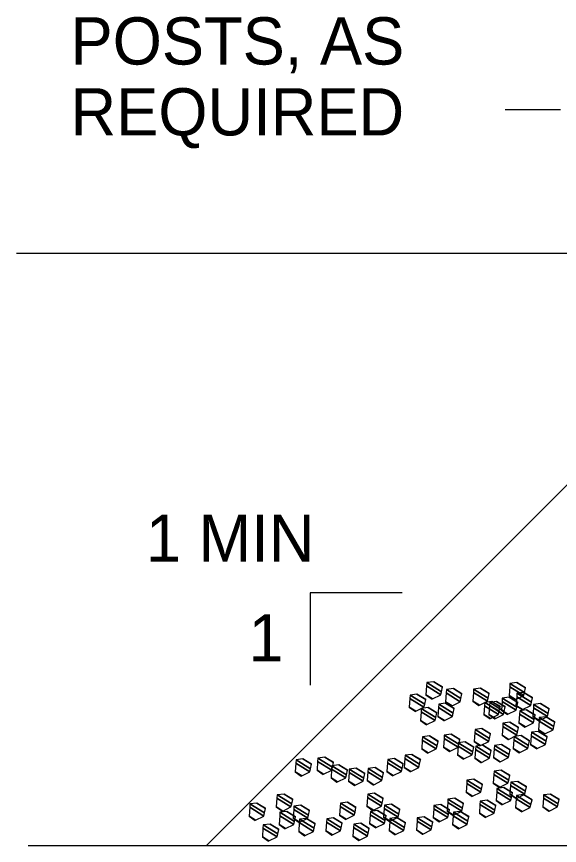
# Model space of a CAD drawing. Extents: x 636462 to 639049, y 299944 to 300538.
# Drawn here: x 637684.5 to 637718.9, y 300291.8 to 300344.3 of the extents above; entities that cross this region are included whole.
import ezdxf

# ---------------------------------------------------------------- set-up
doc = ezdxf.new("R2010")
doc.units = 0
doc.layers.add('Default', color=7, linetype='Continuous')

msp = doc.modelspace()

# ---------------------------------------------------------------- linework, layer by layer
at = {"layer": 'Default'}
for p, q in [((637715.459, 300338.433), (637718.957, 300338.433)), ((637684.462, 300329.325), (637739.67, 300329.325)), ((637696.5, 300291.751), (637727.952, 300323.205)), ((637685.207, 300291.751), (637853.724, 300291.751))]:
    msp.add_line(p, q, dxfattribs=at)
msp.add_lwpolyline([(637708.916, 300307.763), (637703.079, 300307.763), (637703.079, 300301.925)], dxfattribs=at)
for points in [[(637710.468, 300301.866), (637711.365, 300301.31), (637711.408, 300301.503), (637710.484, 300302.076)], [(637710.484, 300302.076), (637711.408, 300301.503), (637711.472, 300301.792), (637710.923, 300302.133)], [(637710.923, 300302.133), (637711.472, 300301.792), (637711.475, 300301.805), (637711.475, 300301.805)], [(637715.737, 300301.808), (637716.626, 300301.257), (637716.67, 300301.452), (637715.752, 300302.022)], [(637715.752, 300302.022), (637716.67, 300301.452), (637716.735, 300301.737), (637716.187, 300302.076)], [(637716.187, 300302.076), (637716.735, 300301.737), (637716.737, 300301.749), (637716.737, 300301.749)], [(637710.427, 300301.31), (637710.844, 300301.051), (637711.365, 300301.31), (637710.468, 300301.866)], [(637711.669, 300300.869), (637712.084, 300300.611), (637712.597, 300300.869), (637711.708, 300301.42)], [(637711.708, 300301.42), (637712.597, 300300.869), (637712.642, 300301.066), (637711.723, 300301.635)], [(637711.723, 300301.635), (637712.642, 300301.066), (637712.707, 300301.356), (637712.162, 300301.694)], [(637712.162, 300301.694), (637712.707, 300301.356), (637712.708, 300301.362), (637712.708, 300301.362)], [(637713.396, 300300.905), (637713.815, 300300.646), (637714.328, 300300.905), (637713.434, 300301.46)], [(637713.434, 300301.46), (637714.328, 300300.905), (637714.371, 300301.098), (637713.449, 300301.67)], [(637713.449, 300301.67), (637714.371, 300301.098), (637714.435, 300301.384), (637713.885, 300301.724)], [(637713.885, 300301.724), (637714.435, 300301.384), (637714.438, 300301.397), (637714.438, 300301.397)], [(637715.698, 300301.257), (637716.115, 300300.998), (637716.626, 300301.257), (637715.737, 300301.808)], [(637716.195, 300301.405), (637717.114, 300300.835), (637717.178, 300301.122), (637716.634, 300301.459)], [(637716.634, 300301.459), (637717.178, 300301.122), (637717.18, 300301.132), (637717.18, 300301.132)], [(637709.369, 300300.513), (637709.783, 300300.256), (637710.3, 300300.513), (637709.408, 300301.065)], [(637709.408, 300301.065), (637710.3, 300300.513), (637710.344, 300300.713), (637709.424, 300301.283)], [(637709.424, 300301.283), (637710.344, 300300.713), (637710.408, 300300.996), (637709.857, 300301.338)], [(637709.857, 300301.338), (637710.408, 300300.996), (637710.411, 300301.01), (637710.411, 300301.01)], [(637710.811, 300301.035), (637710.811, 300301.035), (637710.844, 300301.051), (637710.427, 300301.31)], [(637713.78, 300300.628), (637713.78, 300300.628), (637713.815, 300300.646), (637713.396, 300300.905)], [(637715.249, 300300.883), (637716.141, 300300.331), (637716.184, 300300.525), (637715.265, 300301.095)], [(637715.265, 300301.095), (637716.184, 300300.525), (637716.248, 300300.811), (637715.704, 300301.148)], [(637716.08, 300300.98), (637716.08, 300300.98), (637716.115, 300300.998), (637715.698, 300301.257)], [(637715.704, 300301.148), (637716.248, 300300.811), (637716.25, 300300.82), (637716.25, 300300.82)], [(637716.136, 300300.634), (637716.551, 300300.377), (637717.069, 300300.634), (637716.179, 300301.186)], [(637716.179, 300301.186), (637717.069, 300300.634), (637717.114, 300300.835), (637716.195, 300301.405)], [(637709.754, 300300.242), (637709.754, 300300.242), (637709.783, 300300.256), (637709.369, 300300.513)], [(637710.115, 300300.227), (637711.007, 300299.673), (637711.051, 300299.874), (637710.132, 300300.444)], [(637710.132, 300300.444), (637711.051, 300299.874), (637711.113, 300300.162), (637710.571, 300300.499)], [(637710.571, 300300.499), (637711.113, 300300.162), (637711.115, 300300.171), (637711.115, 300300.171)], [(637711.179, 300299.938), (637711.593, 300299.682), (637712.114, 300299.938), (637711.22, 300300.492)], [(637711.22, 300300.492), (637712.114, 300299.938), (637712.156, 300300.136), (637711.236, 300300.707)], [(637711.236, 300300.707), (637712.156, 300300.136), (637712.219, 300300.426), (637711.675, 300300.764)], [(637712.053, 300300.596), (637712.053, 300300.596), (637712.084, 300300.611), (637711.669, 300300.869)], [(637711.675, 300300.764), (637712.219, 300300.426), (637712.221, 300300.436), (637712.221, 300300.436)], [(637714.102, 300300.062), (637714.521, 300299.802), (637715.032, 300300.062), (637714.143, 300300.613)], [(637714.143, 300300.613), (637715.032, 300300.062), (637715.076, 300300.257), (637714.158, 300300.826)], [(637714.158, 300300.826), (637715.076, 300300.257), (637715.141, 300300.546), (637714.597, 300300.883)], [(637714.411, 300300.062), (637714.829, 300299.803), (637715.346, 300300.062), (637714.452, 300300.616)], [(637714.452, 300300.616), (637715.346, 300300.062), (637715.389, 300300.255), (637714.468, 300300.826)], [(637714.468, 300300.826), (637715.389, 300300.255), (637715.454, 300300.541), (637714.903, 300300.883)], [(637714.597, 300300.883), (637715.141, 300300.546), (637715.143, 300300.555), (637715.143, 300300.555)], [(637714.903, 300300.883), (637715.454, 300300.541), (637715.457, 300300.555), (637715.457, 300300.555)], [(637715.208, 300300.331), (637715.625, 300300.072), (637716.141, 300300.331), (637715.249, 300300.883)], [(637716.523, 300300.363), (637716.523, 300300.363), (637716.551, 300300.377), (637716.136, 300300.634)], [(637717.196, 300299.93), (637717.613, 300299.672), (637718.131, 300299.93), (637717.238, 300300.484)], [(637717.238, 300300.484), (637718.131, 300299.93), (637718.175, 300300.128), (637717.255, 300300.699)], [(637717.255, 300300.699), (637718.175, 300300.128), (637718.239, 300300.41), (637717.692, 300300.749)], [(637717.692, 300300.749), (637718.239, 300300.41), (637718.242, 300300.424), (637718.242, 300300.424)], [(637710.073, 300299.673), (637710.488, 300299.416), (637711.007, 300299.673), (637710.115, 300300.227)], [(637711.564, 300299.667), (637711.564, 300299.667), (637711.593, 300299.682), (637711.179, 300299.938)], [(637714.488, 300299.785), (637714.488, 300299.785), (637714.521, 300299.802), (637714.102, 300300.062)], [(637714.794, 300299.785), (637714.794, 300299.785), (637714.829, 300299.803), (637714.411, 300300.062)], [(637715.592, 300300.056), (637715.592, 300300.056), (637715.625, 300300.072), (637715.208, 300300.331)], [(637716.312, 300299.53), (637716.729, 300299.272), (637717.245, 300299.53), (637716.353, 300300.083)], [(637716.353, 300300.083), (637717.245, 300299.53), (637717.289, 300299.728), (637716.369, 300300.298)], [(637716.369, 300300.298), (637717.289, 300299.728), (637717.352, 300300.017), (637716.81, 300300.353)], [(637716.81, 300300.353), (637717.352, 300300.017), (637717.354, 300300.025), (637717.354, 300300.025)], [(637717.583, 300299.657), (637717.583, 300299.657), (637717.613, 300299.672), (637717.196, 300299.93)], [(637717.595, 300299.639), (637718.483, 300299.089), (637718.529, 300299.288), (637717.611, 300299.858)], [(637717.611, 300299.858), (637718.529, 300299.288), (637718.595, 300299.574), (637718.046, 300299.914)], [(637718.046, 300299.914), (637718.595, 300299.574), (637718.598, 300299.587), (637718.598, 300299.587)], [(637710.459, 300299.402), (637710.459, 300299.402), (637710.488, 300299.416), (637710.073, 300299.673)], [(637715.291, 300299.292), (637716.185, 300298.737), (637716.229, 300298.933), (637715.305, 300299.506)], [(637715.305, 300299.506), (637716.229, 300298.933), (637716.293, 300299.221), (637715.746, 300299.56)], [(637715.746, 300299.56), (637716.293, 300299.221), (637716.294, 300299.227), (637716.294, 300299.227)], [(637716.699, 300299.257), (637716.699, 300299.257), (637716.729, 300299.272), (637716.312, 300299.53)], [(637717.556, 300299.089), (637717.969, 300298.833), (637718.483, 300299.089), (637717.595, 300299.639)], [(637711.59, 300298.751), (637712.513, 300298.179), (637712.577, 300298.47), (637712.029, 300298.81)], [(637712.029, 300298.81), (637712.577, 300298.47), (637712.579, 300298.48), (637712.579, 300298.48)], [(637713.481, 300298.337), (637713.895, 300298.08), (637714.415, 300298.337), (637713.523, 300298.89)], [(637713.523, 300298.89), (637714.415, 300298.337), (637714.46, 300298.535), (637713.54, 300299.105)], [(637713.54, 300299.105), (637714.46, 300298.535), (637714.524, 300298.822), (637713.976, 300299.162)], [(637713.976, 300299.162), (637714.524, 300298.822), (637714.527, 300298.834), (637714.527, 300298.834)], [(637715.253, 300298.737), (637715.667, 300298.48), (637716.185, 300298.737), (637715.291, 300299.292)], [(637717.105, 300298.712), (637717.997, 300298.159), (637718.041, 300298.359), (637717.121, 300298.929)], [(637717.121, 300298.929), (637718.041, 300298.359), (637718.105, 300298.648), (637717.562, 300298.984)], [(637717.939, 300298.818), (637717.939, 300298.818), (637717.969, 300298.833), (637717.556, 300299.089)], [(637717.562, 300298.984), (637718.105, 300298.648), (637718.106, 300298.656), (637718.106, 300298.656)], [(637710.154, 300297.873), (637710.572, 300297.614), (637711.082, 300297.873), (637710.193, 300298.425)], [(637710.193, 300298.425), (637711.082, 300297.873), (637711.128, 300298.07), (637710.209, 300298.64)], [(637710.209, 300298.64), (637711.128, 300298.07), (637711.193, 300298.353), (637710.645, 300298.693)], [(637710.645, 300298.693), (637711.193, 300298.353), (637711.196, 300298.363), (637711.196, 300298.363)], [(637711.537, 300297.985), (637711.952, 300297.728), (637712.47, 300297.985), (637711.575, 300298.539)], [(637711.575, 300298.539), (637712.47, 300297.985), (637712.513, 300298.179), (637711.59, 300298.751)], [(637712.46, 300298.048), (637713.352, 300297.495), (637713.395, 300297.694), (637712.476, 300298.264)], [(637712.476, 300298.264), (637713.395, 300297.694), (637713.459, 300297.985), (637712.919, 300298.32)], [(637712.919, 300298.32), (637713.459, 300297.985), (637713.461, 300297.993), (637713.461, 300297.993)], [(637713.865, 300298.066), (637713.865, 300298.066), (637713.895, 300298.08), (637713.481, 300298.337)], [(637715.639, 300298.466), (637715.639, 300298.466), (637715.667, 300298.48), (637715.253, 300298.737)], [(637715.961, 300297.896), (637716.376, 300297.638), (637716.891, 300297.896), (637716.001, 300298.447)], [(637716.001, 300298.447), (637716.891, 300297.896), (637716.936, 300298.095), (637716.017, 300298.664)], [(637716.017, 300298.664), (637716.936, 300298.095), (637717.001, 300298.382), (637716.454, 300298.721)], [(637716.454, 300298.721), (637717.001, 300298.382), (637717.002, 300298.389), (637717.002, 300298.389)], [(637717.065, 300298.159), (637717.479, 300297.902), (637717.997, 300298.159), (637717.105, 300298.712)], [(637710.54, 300297.598), (637710.54, 300297.598), (637710.572, 300297.614), (637710.154, 300297.873)], [(637711.924, 300297.714), (637711.924, 300297.714), (637711.952, 300297.728), (637711.537, 300297.985)], [(637712.421, 300297.495), (637712.837, 300297.238), (637713.352, 300297.495), (637712.46, 300298.048)], [(637713.527, 300297.279), (637713.945, 300297.02), (637714.46, 300297.279), (637713.567, 300297.832)], [(637713.567, 300297.832), (637714.46, 300297.279), (637714.503, 300297.472), (637713.582, 300298.043)], [(637713.582, 300298.043), (637714.503, 300297.472), (637714.568, 300297.764), (637714.023, 300298.102)], [(637714.023, 300298.102), (637714.568, 300297.764), (637714.569, 300297.768), (637714.569, 300297.768)], [(637714.719, 300297.319), (637715.133, 300297.062), (637715.655, 300297.319), (637714.761, 300297.874)], [(637714.761, 300297.874), (637715.655, 300297.319), (637715.698, 300297.519), (637714.777, 300298.09)], [(637714.777, 300298.09), (637715.698, 300297.519), (637715.759, 300297.808), (637715.216, 300298.144)], [(637715.216, 300298.144), (637715.759, 300297.808), (637715.76, 300297.815), (637715.76, 300297.815)], [(637716.345, 300297.623), (637716.345, 300297.623), (637716.376, 300297.638), (637715.961, 300297.896)], [(637717.451, 300297.888), (637717.451, 300297.888), (637717.479, 300297.902), (637717.065, 300298.159)], [(637702.187, 300297.184), (637703.111, 300296.611), (637703.174, 300296.895), (637702.624, 300297.236)], [(637702.624, 300297.236), (637703.174, 300296.895), (637703.176, 300296.905), (637703.176, 300296.905)], [(637703.556, 300297.08), (637704.449, 300296.527), (637704.492, 300296.724), (637703.571, 300297.295)], [(637703.571, 300297.295), (637704.492, 300296.724), (637704.556, 300297.014), (637704.012, 300297.352)], [(637704.012, 300297.352), (637704.556, 300297.014), (637704.558, 300297.024), (637704.558, 300297.024)], [(637707.998, 300297.208), (637708.918, 300296.638), (637708.985, 300296.923), (637708.433, 300297.265)], [(637708.433, 300297.265), (637708.985, 300296.923), (637708.987, 300296.933), (637708.987, 300296.933)], [(637709.05, 300296.702), (637709.461, 300296.448), (637709.978, 300296.702), (637709.087, 300297.255)], [(637709.087, 300297.255), (637709.978, 300296.702), (637710.023, 300296.9), (637709.102, 300297.471)], [(637709.102, 300297.471), (637710.023, 300296.9), (637710.088, 300297.186), (637709.537, 300297.528)], [(637709.537, 300297.528), (637710.088, 300297.186), (637710.091, 300297.198), (637710.091, 300297.198)], [(637712.805, 300297.222), (637712.805, 300297.222), (637712.837, 300297.238), (637712.421, 300297.495)], [(637713.91, 300297.002), (637713.91, 300297.002), (637713.945, 300297.02), (637713.527, 300297.279)], [(637715.105, 300297.048), (637715.105, 300297.048), (637715.133, 300297.062), (637714.719, 300297.319)], [(637702.135, 300296.415), (637702.55, 300296.158), (637703.067, 300296.415), (637702.173, 300296.97)], [(637702.173, 300296.97), (637703.067, 300296.415), (637703.111, 300296.611), (637702.187, 300297.184)], [(637703.516, 300296.527), (637703.931, 300296.269), (637704.449, 300296.527), (637703.556, 300297.08)], [(637704.442, 300296.594), (637705.334, 300296.041), (637705.379, 300296.236), (637704.457, 300296.808)], [(637704.457, 300296.808), (637705.379, 300296.236), (637705.443, 300296.522), (637704.891, 300296.864)], [(637704.891, 300296.864), (637705.443, 300296.522), (637705.446, 300296.533), (637705.446, 300296.533)], [(637706.758, 300296.63), (637707.676, 300296.06), (637707.741, 300296.349), (637707.197, 300296.686)], [(637707.197, 300296.686), (637707.741, 300296.349), (637707.743, 300296.359), (637707.743, 300296.359)], [(637707.937, 300296.44), (637708.354, 300296.181), (637708.872, 300296.44), (637707.981, 300296.992)], [(637707.981, 300296.992), (637708.872, 300296.44), (637708.918, 300296.638), (637707.998, 300297.208)], [(637709.428, 300296.431), (637709.428, 300296.431), (637709.461, 300296.448), (637709.05, 300296.702)], [(637702.519, 300296.142), (637702.519, 300296.142), (637702.55, 300296.158), (637702.135, 300296.415)], [(637703.898, 300296.253), (637703.898, 300296.253), (637703.931, 300296.269), (637703.516, 300296.527)], [(637704.404, 300296.041), (637704.819, 300295.784), (637705.334, 300296.041), (637704.442, 300296.594)], [(637705.508, 300295.823), (637705.926, 300295.564), (637706.439, 300295.823), (637705.549, 300296.374)], [(637705.549, 300296.374), (637706.439, 300295.823), (637706.483, 300296.016), (637705.565, 300296.585)], [(637705.565, 300296.585), (637706.483, 300296.016), (637706.549, 300296.307), (637706.002, 300296.646)], [(637706.002, 300296.646), (637706.549, 300296.307), (637706.55, 300296.312), (637706.55, 300296.312)], [(637706.702, 300295.861), (637707.116, 300295.604), (637707.632, 300295.861), (637706.742, 300296.413)], [(637706.742, 300296.413), (637707.632, 300295.861), (637707.676, 300296.06), (637706.758, 300296.63)], [(637708.324, 300296.167), (637708.324, 300296.167), (637708.354, 300296.181), (637707.937, 300296.44)], [(637714.694, 300295.701), (637715.111, 300295.443), (637715.627, 300295.701), (637714.737, 300296.253)], [(637714.737, 300296.253), (637715.627, 300295.701), (637715.672, 300295.9), (637714.753, 300296.47)], [(637714.753, 300296.47), (637715.672, 300295.9), (637715.736, 300296.188), (637715.19, 300296.527)], [(637715.19, 300296.527), (637715.736, 300296.188), (637715.738, 300296.197), (637715.738, 300296.197)], [(637704.782, 300295.766), (637704.782, 300295.766), (637704.819, 300295.784), (637704.404, 300296.041)], [(637705.895, 300295.548), (637705.895, 300295.548), (637705.926, 300295.564), (637705.508, 300295.823)], [(637707.088, 300295.59), (637707.088, 300295.59), (637707.116, 300295.604), (637706.702, 300295.861)], [(637712.969, 300295.125), (637713.384, 300294.868), (637713.904, 300295.125), (637713.011, 300295.678)], [(637713.011, 300295.678), (637713.904, 300295.125), (637713.948, 300295.323), (637713.028, 300295.893)], [(637713.028, 300295.893), (637713.948, 300295.323), (637714.012, 300295.608), (637713.461, 300295.95)], [(637713.461, 300295.95), (637714.012, 300295.608), (637714.015, 300295.62), (637714.015, 300295.62)], [(637715.081, 300295.428), (637715.081, 300295.428), (637715.111, 300295.443), (637714.694, 300295.701)], [(637715.797, 300295.551), (637716.689, 300294.998), (637716.734, 300295.191), (637715.813, 300295.762)], [(637715.813, 300295.762), (637716.734, 300295.191), (637716.799, 300295.472), (637716.25, 300295.813)], [(637716.25, 300295.813), (637716.799, 300295.472), (637716.802, 300295.485), (637716.802, 300295.485)], [(637713.352, 300294.852), (637713.352, 300294.852), (637713.384, 300294.868), (637712.969, 300295.125)], [(637714.872, 300294.597), (637715.288, 300294.34), (637715.803, 300294.597), (637714.912, 300295.15)], [(637714.912, 300295.15), (637715.803, 300294.597), (637715.847, 300294.795), (637714.927, 300295.366)], [(637714.927, 300295.366), (637715.847, 300294.795), (637715.912, 300295.086), (637715.37, 300295.422)], [(637715.37, 300295.422), (637715.912, 300295.086), (637715.912, 300295.089), (637715.912, 300295.089)], [(637715.754, 300294.998), (637716.172, 300294.738), (637716.689, 300294.998), (637715.797, 300295.551)], [(637700.935, 300294.189), (637701.352, 300293.93), (637701.866, 300294.189), (637700.976, 300294.74)], [(637700.976, 300294.74), (637701.866, 300294.189), (637701.91, 300294.386), (637700.992, 300294.955)], [(637700.992, 300294.955), (637701.91, 300294.386), (637701.976, 300294.674), (637701.431, 300295.012)], [(637701.431, 300295.012), (637701.976, 300294.674), (637701.977, 300294.68), (637701.977, 300294.68)], [(637706.677, 300294.245), (637707.093, 300293.988), (637707.608, 300294.245), (637706.717, 300294.798)], [(637706.717, 300294.798), (637707.608, 300294.245), (637707.652, 300294.441), (637706.732, 300295.012)], [(637706.732, 300295.012), (637707.652, 300294.441), (637707.716, 300294.728), (637707.167, 300295.068)], [(637707.167, 300295.068), (637707.716, 300294.728), (637707.719, 300294.741), (637707.719, 300294.741)], [(637711.805, 300294.476), (637712.696, 300293.924), (637712.74, 300294.122), (637711.821, 300294.692)], [(637711.821, 300294.692), (637712.74, 300294.122), (637712.803, 300294.409), (637712.259, 300294.747)], [(637712.259, 300294.747), (637712.803, 300294.409), (637712.805, 300294.419), (637712.805, 300294.419)], [(637713.865, 300294.567), (637714.786, 300293.996), (637714.85, 300294.283), (637714.304, 300294.621)], [(637714.304, 300294.621), (637714.85, 300294.283), (637714.852, 300294.292), (637714.852, 300294.292)], [(637715.257, 300294.324), (637715.257, 300294.324), (637715.288, 300294.34), (637714.872, 300294.597)], [(637716.141, 300294.722), (637716.141, 300294.722), (637716.172, 300294.738), (637715.754, 300294.998)], [(637716.114, 300294.154), (637716.528, 300293.898), (637717.041, 300294.154), (637716.152, 300294.705)], [(637716.152, 300294.705), (637717.041, 300294.154), (637717.086, 300294.349), (637716.167, 300294.919)], [(637716.167, 300294.919), (637717.086, 300294.349), (637717.153, 300294.637), (637716.604, 300294.977)], [(637716.604, 300294.977), (637717.153, 300294.637), (637717.156, 300294.648), (637717.156, 300294.648)], [(637717.835, 300294.189), (637718.25, 300293.931), (637718.772, 300294.189), (637717.875, 300294.745)], [(637717.875, 300294.745), (637718.772, 300294.189), (637718.814, 300294.382), (637717.89, 300294.955)], [(637717.89, 300294.955), (637718.814, 300294.382), (637718.877, 300294.672), (637718.333, 300295.01)], [(637718.333, 300295.01), (637718.877, 300294.672), (637718.879, 300294.68), (637718.879, 300294.68)], [(637699.208, 300293.612), (637699.625, 300293.354), (637700.143, 300293.612), (637699.246, 300294.168)], [(637699.246, 300294.168), (637700.143, 300293.612), (637700.185, 300293.808), (637699.261, 300294.381)], [(637699.261, 300294.381), (637700.185, 300293.808), (637700.249, 300294.1), (637699.704, 300294.437)], [(637699.704, 300294.437), (637700.249, 300294.1), (637700.25, 300294.106), (637700.25, 300294.106)], [(637701.322, 300293.915), (637701.322, 300293.915), (637701.352, 300293.93), (637700.935, 300294.189)], [(637702.036, 300294.038), (637702.932, 300293.483), (637702.973, 300293.675), (637702.05, 300294.247)], [(637702.05, 300294.247), (637702.973, 300293.675), (637703.035, 300293.961), (637702.489, 300294.3)], [(637702.489, 300294.3), (637703.035, 300293.961), (637703.037, 300293.97), (637703.037, 300293.97)], [(637704.948, 300293.667), (637705.363, 300293.41), (637705.882, 300293.667), (637704.99, 300294.22)], [(637704.99, 300294.22), (637705.882, 300293.667), (637705.926, 300293.867), (637705.007, 300294.437)], [(637705.007, 300294.437), (637705.926, 300293.867), (637705.988, 300294.156), (637705.446, 300294.492)], [(637705.446, 300294.492), (637705.988, 300294.156), (637705.99, 300294.164), (637705.99, 300294.164)], [(637707.058, 300293.97), (637707.058, 300293.97), (637707.093, 300293.988), (637706.677, 300294.245)], [(637707.737, 300293.539), (637708.153, 300293.281), (637708.671, 300293.539), (637707.777, 300294.094)], [(637707.777, 300294.094), (637708.671, 300293.539), (637708.713, 300293.734), (637707.792, 300294.306)], [(637707.792, 300294.306), (637708.713, 300293.734), (637708.775, 300294.021), (637708.231, 300294.358)], [(637708.231, 300294.358), (637708.775, 300294.021), (637708.777, 300294.029), (637708.777, 300294.029)], [(637710.882, 300293.527), (637711.3, 300293.268), (637711.81, 300293.527), (637710.92, 300294.079)], [(637710.92, 300294.079), (637711.81, 300293.527), (637711.855, 300293.721), (637710.935, 300294.292)], [(637710.935, 300294.292), (637711.855, 300293.721), (637711.921, 300294.008), (637711.372, 300294.348)], [(637711.372, 300294.348), (637711.921, 300294.008), (637711.924, 300294.019), (637711.924, 300294.019)], [(637711.766, 300293.924), (637712.18, 300293.667), (637712.696, 300293.924), (637711.805, 300294.476)], [(637713.811, 300293.802), (637714.229, 300293.543), (637714.743, 300293.802), (637713.85, 300294.356)], [(637713.85, 300294.356), (637714.743, 300293.802), (637714.786, 300293.996), (637713.865, 300294.567)], [(637716.499, 300293.883), (637716.499, 300293.883), (637716.528, 300293.898), (637716.114, 300294.154)], [(637718.218, 300293.915), (637718.218, 300293.915), (637718.25, 300293.931), (637717.835, 300294.189)], [(637699.595, 300293.339), (637699.595, 300293.339), (637699.625, 300293.354), (637699.208, 300293.612)], [(637701.113, 300293.082), (637701.526, 300292.826), (637702.046, 300293.082), (637701.153, 300293.636)], [(637701.153, 300293.636), (637702.046, 300293.082), (637702.09, 300293.279), (637701.168, 300293.851)], [(637701.168, 300293.851), (637702.09, 300293.279), (637702.154, 300293.567), (637701.605, 300293.907)], [(637701.605, 300293.907), (637702.154, 300293.567), (637702.155, 300293.572), (637702.155, 300293.572)], [(637701.997, 300293.483), (637702.415, 300293.224), (637702.932, 300293.483), (637702.036, 300294.038)], [(637705.334, 300293.396), (637705.334, 300293.396), (637705.363, 300293.41), (637704.948, 300293.667)], [(637706.855, 300293.139), (637707.271, 300292.881), (637707.786, 300293.139), (637706.893, 300293.692)], [(637706.893, 300293.692), (637707.786, 300293.139), (637707.83, 300293.336), (637706.908, 300293.907)], [(637706.908, 300293.907), (637707.83, 300293.336), (637707.894, 300293.622), (637707.343, 300293.964)], [(637707.343, 300293.964), (637707.894, 300293.622), (637707.897, 300293.636), (637707.897, 300293.636)], [(637708.119, 300293.264), (637708.119, 300293.264), (637708.153, 300293.281), (637707.737, 300293.539)], [(637709.875, 300293.499), (637710.793, 300292.93), (637710.857, 300293.216), (637710.31, 300293.555)], [(637710.31, 300293.555), (637710.857, 300293.216), (637710.86, 300293.228), (637710.86, 300293.228)], [(637712.148, 300293.651), (637712.148, 300293.651), (637712.18, 300293.667), (637711.766, 300293.924)], [(637712.118, 300293.082), (637712.531, 300292.826), (637713.048, 300293.082), (637712.157, 300293.635)], [(637712.157, 300293.635), (637713.048, 300293.082), (637713.092, 300293.281), (637712.172, 300293.851)], [(637712.172, 300293.851), (637713.092, 300293.281), (637713.155, 300293.57), (637712.611, 300293.907)], [(637712.611, 300293.907), (637713.155, 300293.57), (637713.157, 300293.58), (637713.157, 300293.58)], [(637714.197, 300293.527), (637714.197, 300293.527), (637714.229, 300293.543), (637713.811, 300293.802)], [(637700.09, 300292.844), (637700.984, 300292.289), (637701.027, 300292.484), (637700.104, 300293.056)], [(637700.104, 300293.056), (637701.027, 300292.484), (637701.091, 300292.767), (637700.543, 300293.106)], [(637700.543, 300293.106), (637701.091, 300292.767), (637701.093, 300292.779), (637701.093, 300292.779)], [(637701.496, 300292.811), (637701.496, 300292.811), (637701.526, 300292.826), (637701.113, 300293.082)], [(637702.38, 300293.206), (637702.38, 300293.206), (637702.415, 300293.224), (637701.997, 300293.483)], [(637702.353, 300292.643), (637702.769, 300292.385), (637703.284, 300292.643), (637702.391, 300293.197)], [(637702.391, 300293.197), (637703.284, 300292.643), (637703.327, 300292.837), (637702.406, 300293.408)], [(637702.406, 300293.408), (637703.327, 300292.837), (637703.391, 300293.119), (637702.841, 300293.46)], [(637702.841, 300293.46), (637703.391, 300293.119), (637703.395, 300293.135), (637703.395, 300293.135)], [(637704.076, 300292.674), (637704.49, 300292.417), (637705.009, 300292.674), (637704.117, 300293.227)], [(637704.117, 300293.227), (637705.009, 300292.674), (637705.053, 300292.874), (637704.133, 300293.444)], [(637704.133, 300293.444), (637705.053, 300292.874), (637705.116, 300293.158), (637704.572, 300293.495)], [(637704.572, 300293.495), (637705.116, 300293.158), (637705.118, 300293.167), (637705.118, 300293.167)], [(637705.83, 300292.897), (637706.722, 300292.344), (637706.765, 300292.539), (637705.846, 300293.109)], [(637705.846, 300293.109), (637706.765, 300292.539), (637706.829, 300292.827), (637706.287, 300293.163)], [(637706.287, 300293.163), (637706.829, 300292.827), (637706.831, 300292.835), (637706.831, 300292.835)], [(637707.24, 300292.866), (637707.24, 300292.866), (637707.271, 300292.881), (637706.855, 300293.139)], [(637708.093, 300292.698), (637708.504, 300292.443), (637709.025, 300292.698), (637708.13, 300293.253)], [(637708.13, 300293.253), (637709.025, 300292.698), (637709.069, 300292.893), (637708.144, 300293.466)], [(637708.144, 300293.466), (637709.069, 300292.893), (637709.133, 300293.18), (637708.587, 300293.519)], [(637708.587, 300293.519), (637709.133, 300293.18), (637709.135, 300293.189), (637709.135, 300293.189)], [(637709.818, 300292.73), (637710.232, 300292.474), (637710.749, 300292.73), (637709.859, 300293.282)], [(637709.859, 300293.282), (637710.749, 300292.73), (637710.793, 300292.93), (637709.875, 300293.499)], [(637711.264, 300293.25), (637711.264, 300293.25), (637711.3, 300293.268), (637710.882, 300293.527)], [(637712.5, 300292.811), (637712.5, 300292.811), (637712.531, 300292.826), (637712.118, 300293.082)], [(637700.052, 300292.289), (637700.467, 300292.032), (637700.984, 300292.289), (637700.09, 300292.844)], [(637702.731, 300292.366), (637702.731, 300292.366), (637702.769, 300292.385), (637702.353, 300292.643)], [(637704.461, 300292.403), (637704.461, 300292.403), (637704.49, 300292.417), (637704.076, 300292.674)], [(637705.789, 300292.344), (637706.208, 300292.084), (637706.722, 300292.344), (637705.83, 300292.897)], [(637708.471, 300292.427), (637708.471, 300292.427), (637708.504, 300292.443), (637708.093, 300292.698)], [(637710.203, 300292.459), (637710.203, 300292.459), (637710.232, 300292.474), (637709.818, 300292.73)], [(637700.432, 300292.014), (637700.432, 300292.014), (637700.467, 300292.032), (637700.052, 300292.289)], [(637706.174, 300292.067), (637706.174, 300292.067), (637706.208, 300292.084), (637705.789, 300292.344)]]:
    msp.add_lwpolyline(points, close=True, dxfattribs=at)

# ---------------------------------------------------------------- texts
for s, p in [('POSTS, AS', (637687.885, 300341.277)), ('REQUIRED', (637687.885, 300336.78)), ('1 MIN', (637692.661, 300309.739)), ('1', (637699.166, 300303.419))]:
    msp.add_text(s, height=2.998, dxfattribs=at).set_placement(p)

doc.saveas('drawing.dxf')
